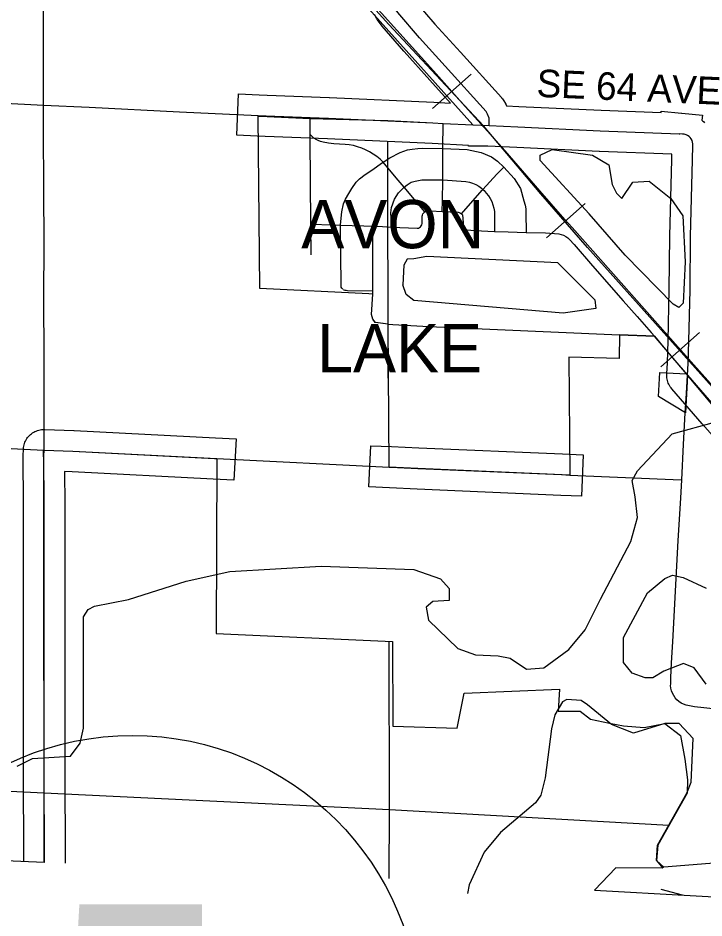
# Model space of a CAD drawing. Extents: x -1403959 to 81668, y -1400582 to 11018.
# Drawn here: x 7735.1 to 7831.3, y 7708.3 to 7834.6 of the extents above; entities that cross this region are included whole.
import ezdxf

# ---------------------------------------------------------------- set-up
doc = ezdxf.new("R2010")
doc.units = 0
for name, color, linetype in [('tdCiCityCartoExten', 7, 'Continuous'), ('tdCiCityDivCarto', 7, 'Continuous'), ('tdCiCoBndryTxt', 7, 'Continuous'), ('tdCiMapFrame', 7, 'Continuous'), ('tdCiRRCL', 7, 'Continuous'), ('tdCiSectLine', 7, 'Continuous'), ('tdCiSectNmbr', 7, 'Continuous'), ('tdCiSectTwpRng', 7, 'Continuous'), ('tdCoCityStreetMajor', 7, 'Continuous'), ('tdCoCityStreetMinor', 7, 'Continuous'), ('tdCoClipBndry', 7, 'Continuous'), ('tdCoSecRteBand', 7, 'Continuous'), ('tdCoSectNmbr', 7, 'Continuous'), ('tdCoStrucSecCoName', 7, 'Continuous'), ('tdCoSurfAsphalt', 7, 'Continuous'), ('tdCoSurfBitum', 7, 'Continuous')]:
    doc.layers.add(name, color=color, linetype=linetype)

msp = doc.modelspace()

# ---------------------------------------------------------------- linework, layer by layer
at = {"layer": 'tdCiCityCartoExten'}
for points in [[(7780.66, 7796.51), (7780.75, 7796.45), (7780.91, 7796.39), (7781.08, 7796.38), (7781.28, 7796.35)], [(7762.61, 7772.78), (7762.8, 7772.77), (7762.93, 7772.77)], [(7787.19, 7771.56), (7787.3, 7771.56)], [(7811.3, 7770.52), (7811.35, 7770.52)], [(7811.35, 7770.52), (7812.44, 7770.47)]]:
    msp.add_lwpolyline(points, dxfattribs=at)
at = {"layer": 'tdCiCityDivCarto'}
for points in [[(7776.02, 7820.49), (7776.06, 7820.6)], [(7776.17, 7801.37), (7776.14, 7805.6), (7776.14, 7805.66), (7776.06, 7817.66), (7776.05, 7818.21), (7776.02, 7820.49)], [(7794.63, 7811.87), (7794.64, 7816.28), (7794.69, 7819.77)], [(7786.25, 7814.38), (7785.84, 7814.77), (7785.37, 7815.15), (7784.87, 7815.49), (7784.36, 7815.8), (7783.82, 7816.07), (7783.27, 7816.31), (7782.7, 7816.5), (7782.12, 7816.66), (7781.53, 7816.77), (7780.93, 7816.84), (7780.15, 7816.86), (7779.38, 7816.91), (7778.61, 7817), (7777.84, 7817.13), (7777.5, 7817.23), (7777.17, 7817.36), (7776.86, 7817.53), (7776.57, 7817.73), (7776.3, 7817.95), (7776.05, 7818.21)], [(7787.19, 7814.94), (7788.66, 7815.71), (7789.67, 7816.08), (7790.33, 7816.19), (7791.14, 7816.27), (7791.78, 7816.33), (7794.64, 7816.28)], [(7794.64, 7816.28), (7798.06, 7816.1), (7800, 7815.69), (7801.45, 7815.07), (7802.33, 7814.49), (7803.18, 7813.66), (7804.64, 7812.07), (7805.53, 7810.65), (7806.01, 7808.92), (7806.17, 7808.33), (7806.26, 7807.82), (7806.29, 7807.26), (7806.34, 7804.5)], [(7780.6, 7796.55), (7780.49, 7796.67), (7780.41, 7796.82), (7780.37, 7796.99), (7780.37, 7797.16), (7780.29, 7805.52), (7780.29, 7805.54), (7780.46, 7807.37), (7780.71, 7808.51), (7781.01, 7809.15), (7781.46, 7809.96), (7781.87, 7810.63), (7782.51, 7811.52), (7782.94, 7811.99), (7783.73, 7812.6), (7784.71, 7813.22), (7786.16, 7814.29)], [(7786.16, 7814.29), (7786.28, 7814.36), (7787.19, 7814.94)], [(7788.12, 7812.14), (7786.28, 7814.36), (7786.25, 7814.38)], [(7797.25, 7807.1), (7800.17, 7810.43), (7800.25, 7810.51), (7802.23, 7812.65), (7803.18, 7813.66)], [(7789.21, 7810.83), (7788.12, 7812.14)], [(7789.18, 7810.81), (7789.21, 7810.83), (7789.64, 7811.18), (7790.22, 7811.53), (7790.75, 7811.7), (7791.72, 7811.86), (7792.59, 7811.85), (7793.64, 7811.87), (7794.63, 7811.87)], [(7794.57, 7807.42), (7794.57, 7807.45), (7794.61, 7808.87), (7794.63, 7811.87)], [(7794.63, 7811.87), (7794.63, 7811.87), (7797.89, 7811.65), (7798.36, 7811.54), (7798.81, 7811.39), (7799.25, 7811.2), (7799.67, 7810.96), (7800.06, 7810.69), (7800.25, 7810.51), (7800.42, 7810.37), (7800.74, 7810.02), (7801.04, 7809.64), (7801.29, 7809.24), (7801.5, 7808.81), (7801.67, 7808.36), (7801.79, 7807.9), (7801.87, 7807.43), (7801.9, 7806.95), (7801.9, 7805.42), (7801.9, 7804.67)], [(7787.41, 7805.24), (7787.41, 7805.26), (7787.38, 7806.54), (7787.37, 7807.22), (7787.44, 7807.98), (7787.88, 7809.15), (7788.41, 7810.04), (7788.69, 7810.32), (7789.18, 7810.81)], [(7792.1, 7807.36), (7789.21, 7810.83)], [(7787.41, 7805.24), (7787.41, 7805.24), (7789.84, 7805.12), (7791.06, 7805.07), (7791.23, 7805.1), (7791.38, 7805.17), (7791.51, 7805.28), (7791.62, 7805.41), (7791.69, 7805.56), (7791.73, 7805.72), (7791.76, 7805.89), (7791.75, 7806.75), (7791.78, 7806.93), (7791.86, 7807.1), (7791.96, 7807.24), (7792.1, 7807.36)], [(7792.1, 7807.36), (7792.27, 7807.46), (7792.46, 7807.52), (7792.89, 7807.5), (7794.57, 7807.42)], [(7792.1, 7807.36), (7792.1, 7807.36)], [(7794.57, 7807.42), (7796.77, 7807.31), (7796.95, 7807.28), (7797.11, 7807.21), (7797.25, 7807.1), (7797.32, 7807.03), (7797.38, 7806.94), (7797.54, 7805.31), (7797.57, 7805.17), (7797.64, 7805.05), (7797.74, 7804.95), (7797.86, 7804.89), (7798, 7804.86), (7799.14, 7804.77), (7801.9, 7804.64), (7803.8, 7804.56), (7806.34, 7804.49)], [(7776.14, 7805.66), (7779.15, 7805.54), (7780.29, 7805.52), (7783.57, 7805.43), (7784.88, 7805.37), (7786.2, 7805.31), (7787.41, 7805.24)], [(7784.84, 7796.28), (7784.85, 7804.15), (7784.88, 7805.37)], [(7801.9, 7804.67), (7801.9, 7804.64)], [(7806.34, 7804.49), (7806.34, 7804.49)], [(7806.34, 7804.49), (7809.05, 7804.42), (7810.89, 7804.3), (7811.23, 7804.22), (7811.56, 7804.1), (7811.87, 7803.93), (7812.15, 7803.73), (7812.41, 7803.49), (7813.06, 7802.81), (7815.63, 7799.8), (7819.93, 7794.92), (7821.9, 7792.71), (7823.84, 7790.48), (7824.32, 7789.92)], [(7781.28, 7796.35), (7784.84, 7796.28)], [(7786.98, 7791.64), (7785.15, 7791.86), (7784.81, 7792.34), (7784.63, 7792.99), (7784.81, 7795.84)], [(7784.81, 7795.84), (7784.84, 7796.28)], [(7784.84, 7796.28), (7784.84, 7796.28)], [(7786.98, 7791.64), (7787.62, 7791.56)], [(7787.62, 7791.56), (7792.66, 7791.3), (7819.41, 7790.13)], [(7819.41, 7790.13), (7824.32, 7789.92)], [(7824.32, 7789.92), (7824.32, 7789.92)], [(7824.32, 7789.92), (7824.32, 7789.92)], [(7824.32, 7789.92), (7824.97, 7789.17), (7826.83, 7786.92), (7828.94, 7784.47)], [(7828.64, 7779.19), (7828.79, 7781.91), (7828.94, 7784.47)]]:
    msp.add_lwpolyline(points, dxfattribs=at)
at = {"layer": 'tdCiCoBndryTxt'}
for points in [[(7801.15, 7819.51), (7801.15, 7820.5), (7800.92, 7821.09), (7800.7, 7821.46), (7794.97, 7827.8), (7791.36, 7831.8), (7788.34, 7835.32), (7787.85, 7835.99), (7787.55, 7836.51), (7787.34, 7837.19), (7787.12, 7838.96), (7787.12, 7847.33), (7787.04, 7868.63)], [(7768.77, 7820.9), (7769.87, 7820.85), (7776.06, 7820.6), (7778.6, 7820.5), (7786.93, 7820.13), (7786.97, 7820.13), (7793.26, 7819.85), (7794.69, 7819.78), (7798.86, 7819.58)], [(7768.77, 7820.9), (7768.77, 7820.9)], [(7798.86, 7819.58), (7801.15, 7819.47), (7805.17, 7819.28), (7816.7, 7818.74), (7827.77, 7818.34), (7827.86, 7818.33)], [(7801.15, 7819.48), (7801.15, 7819.51)], [(7828.94, 7784.47), (7829.04, 7786.09), (7829.14, 7789.24), (7829.3, 7796.44), (7829.39, 7803.9), (7829.53, 7809.29), (7829.65, 7814.68), (7829.69, 7816.67), (7829.7, 7816.91), (7829.66, 7817.15), (7829.59, 7817.38), (7829.48, 7817.6), (7829.33, 7817.79), (7829.16, 7817.96), (7828.96, 7818.1), (7828.74, 7818.2), (7828.5, 7818.26), (7828.26, 7818.29), (7827.86, 7818.33)], [(7828.94, 7784.47), (7833.19, 7779.56), (7835.35, 7777.09)], [(7738.75, 7725.79), (7738.75, 7729.7), (7738.73, 7736.55), (7738.75, 7744.39), (7738.75, 7751.36), (7738.73, 7758.63), (7738.73, 7766.39), (7738.7, 7773.1), (7738.73, 7773.96)]]:
    msp.add_lwpolyline(points, dxfattribs=at)
at = {"layer": 'tdCiMapFrame'}
for points in [[(7738.73, 7773.96), (7738.76, 7773.96), (7742.78, 7773.81), (7762.61, 7772.78)], [(7787.3, 7771.56), (7791.16, 7771.39), (7811.3, 7770.52)], [(7738.78, 7716.15), (7738.79, 7716.69), (7738.78, 7721.34), (7738.75, 7724.47), (7738.75, 7725.79)]]:
    msp.add_lwpolyline(points, dxfattribs=at)
at = {"layer": 'tdCiRRCL'}
msp.add_line((7717.09, 7717.17), (7738.73, 7716.16), dxfattribs=at)
for points in [[(7832.36, 7780.41), (7828.95, 7784.48), (7828.66, 7779.19), (7824.89, 7781.46), (7825.08, 7784.84), (7828.8, 7784.65), (7824.32, 7789.92), (7819.41, 7790.13), (7819.37, 7786.8), (7812.33, 7787.02), (7812.44, 7770.47), (7791.16, 7771.39), (7787.12, 7771.57), (7786.98, 7791.64), (7785.19, 7791.86), (7784.81, 7792.34), (7784.63, 7792.99), (7784.81, 7795.84), (7784.26, 7795.88), (7768.98, 7796.63), (7768.77, 7820.8), (7768.99, 7820.79), (7776.02, 7820.49), (7786.93, 7820.19), (7793.26, 7819.85), (7794.69, 7819.78), (7798.86, 7819.58), (7787.09, 7832.71), (7753.59, 7870.1)], [(7738.73, 7716.16), (7738.75, 7724.1), (7738.71, 7759.16), (7738.71, 7771.98), (7738.63, 7773.96), (7738.76, 7773.96), (7742.78, 7773.81), (7762.94, 7772.77), (7762.85, 7748.24), (7787.59, 7747.1), (7787.62, 7735.26), (7796.65, 7734.95), (7797.62, 7739.89), (7810.99, 7740.43), (7810.81, 7737.35), (7813.89, 7737.35), (7815.34, 7736.23), (7818.01, 7735.69), (7819.96, 7735.29), (7822.86, 7735.04), (7825.76, 7735.63), (7827.96, 7733.93), (7828.57, 7730.63), (7828.94, 7727.73), (7828.88, 7725.87), (7824.77, 7718.54), (7824.62, 7716.4), (7825.48, 7715.32), (7818.9, 7715.4), (7815.93, 7712.27)], [(7815.93, 7712.27), (7882.99, 7708.51), (7883.79, 7708.47)]]:
    msp.add_lwpolyline(points, dxfattribs=at)
at = {"layer": 'tdCiSectLine'}
for points in [[(7790.62, 7837.12), (7793.54, 7833.71), (7797.12, 7829.75), (7797.12, 7829.75), (7802.85, 7823.4), (7802.88, 7823.37), (7803, 7823.22), (7803.11, 7823.07), (7803.2, 7822.93), (7803.42, 7822.56), (7803.43, 7822.54), (7803.52, 7822.37), (7803.57, 7822.26), (7805.31, 7822.17), (7816.82, 7821.63), (7825.24, 7821.33), (7825.25, 7821.5), (7828.09, 7821.22), (7828.14, 7821.22), (7831.03, 7820.94), (7830.96, 7820.23), (7831.07, 7820.14), (7831.17, 7820.05), (7831.34, 7819.88)], [(7833.18, 7775.17), (7831.01, 7777.65), (7830.99, 7777.66), (7826.75, 7782.58), (7826.64, 7782.71), (7826.53, 7782.86), (7826.43, 7783.02), (7826.34, 7783.19), (7826.26, 7783.36), (7826.2, 7783.54), (7826.14, 7783.72), (7826.1, 7783.91), (7826.07, 7784.1), (7826.05, 7784.28), (7826.04, 7784.47), (7826.05, 7784.65), (7826.14, 7786.22), (7826.24, 7789.31), (7826.39, 7796.49), (7826.49, 7803.94), (7826.49, 7803.98), (7826.63, 7809.36), (7826.74, 7814.74), (7826.74, 7814.75), (7826.76, 7815.47), (7816.6, 7815.84), (7816.57, 7815.84), (7805.04, 7816.38), (7805.03, 7816.38), (7800.95, 7816.57), (7798.24, 7816.58), (7798.24, 7816.7), (7793.13, 7816.95), (7778.48, 7817.6), (7769.75, 7817.95), (7769.74, 7817.95), (7768.63, 7818), (7765.74, 7818.13), (7766, 7823.93), (7768.9, 7823.8), (7769.99, 7823.75), (7778.72, 7823.4), (7778.73, 7823.4), (7793.39, 7822.75), (7793.4, 7822.75), (7795.73, 7822.64), (7792.82, 7825.86), (7789.21, 7829.85), (7789.18, 7829.88), (7789.16, 7829.91), (7786.13, 7833.43), (7786.04, 7833.56), (7785.99, 7833.62), (7785.5, 7834.29), (7785.44, 7834.38), (7785.34, 7834.53), (7785.04, 7835.05)], [(7735.88, 7716.29), (7735.89, 7716.72), (7735.88, 7721.32), (7735.85, 7724.44), (7735.85, 7724.47), (7735.85, 7729.7), (7735.83, 7736.55), (7735.83, 7736.55), (7735.83, 7736.56), (7735.85, 7744.4), (7735.85, 7751.36), (7735.83, 7758.62), (7735.83, 7758.63), (7735.83, 7766.38), (7735.8, 7773.08), (7735.8, 7773.1), (7735.8, 7773.19), (7735.83, 7774.05), (7735.83, 7774.15), (7735.85, 7774.34), (7735.88, 7774.53), (7735.92, 7774.71), (7735.98, 7774.89), (7736.05, 7775.07), (7736.12, 7775.24), (7736.21, 7775.41), (7736.31, 7775.57), (7736.42, 7775.73), (7736.54, 7775.87), (7736.67, 7776.01), (7736.81, 7776.14), (7736.96, 7776.26), (7737.11, 7776.37), (7737.28, 7776.47), (7737.44, 7776.56), (7737.62, 7776.64), (7737.79, 7776.71), (7737.98, 7776.76), (7738.16, 7776.81), (7738.35, 7776.84), (7738.54, 7776.86), (7738.73, 7776.86), (7738.83, 7776.86), (7742.89, 7776.71), (7742.93, 7776.71), (7762.76, 7775.68), (7765.65, 7775.53), (7765.35, 7769.74), (7762.46, 7769.89), (7742.65, 7770.91), (7741.61, 7770.95), (7741.63, 7766.4), (7741.63, 7766.39), (7741.63, 7758.63), (7741.65, 7751.37), (7741.65, 7751.36), (7741.65, 7744.39), (7741.65, 7744.39), (7741.63, 7736.55), (7741.65, 7729.71), (7741.65, 7729.7), (7741.65, 7724.48), (7741.68, 7721.36), (7741.68, 7721.35), (7741.7, 7716.7), (7741.7, 7716.69), (7741.7, 7716.63), (7741.68, 7716.02)], [(7814.07, 7767.49), (7811.17, 7767.62), (7791.04, 7768.49), (7791.04, 7768.49), (7787.17, 7768.66), (7784.27, 7768.79), (7784.53, 7774.58), (7787.43, 7774.46), (7791.29, 7774.29), (7811.43, 7773.42), (7814.32, 7773.29), (7814.07, 7767.49)]]:
    msp.add_lwpolyline(points, dxfattribs=at)
at = {"layer": 'tdCiSectNmbr'}
for points in [[(7715.34, 7823.57), (7738.64, 7822.36), (7738.67, 7822.36)], [(7738.73, 7773.96), (7738.76, 7775.15), (7738.73, 7780.03), (7738.75, 7786.95), (7738.7, 7795.3), (7738.72, 7802.95), (7738.7, 7810.45), (7738.64, 7818.96), (7738.64, 7822.35)], [(7738.67, 7822.36), (7745.06, 7822.04), (7757.7, 7821.41), (7768.77, 7820.9)], [(7828.14, 7769.79), (7828.39, 7774.75), (7828.64, 7779.19)], [(7762.93, 7772.77), (7762.94, 7772.77)], [(7762.94, 7772.77), (7787.12, 7771.57)], [(7787.12, 7771.57), (7787.19, 7771.56)], [(7812.44, 7770.47), (7828.08, 7769.79), (7828.14, 7769.79)], [(7832.99, 7737.63), (7829.95, 7737.97), (7828.74, 7738.19), (7828.39, 7738.32), (7828.06, 7738.49), (7827.75, 7738.7), (7827.47, 7738.94), (7827.22, 7739.22), (7827.01, 7739.53), (7826.84, 7739.86), (7826.71, 7740.21), (7826.62, 7740.57), (7826.58, 7740.94), (7826.59, 7741.15), (7826.61, 7742.05), (7826.72, 7744.14), (7826.89, 7747.08), (7827.23, 7753.3), (7827.64, 7761.31), (7828.01, 7767.24), (7828.14, 7769.79)]]:
    msp.add_lwpolyline(points, dxfattribs=at)
at = {"layer": 'tdCiSectTwpRng'}
for points in [[(7738.64, 7822.35), (7738.64, 7822.36), (7738.63, 7836.8)], [(7693.9, 7776.27), (7714, 7775.24), (7738.63, 7773.96), (7738.73, 7773.96)], [(7825.23, 7712.37), (7828.21, 7711.58)]]:
    msp.add_lwpolyline(points, dxfattribs=at)
at = {"layer": 'tdCoCityStreetMajor'}
for points in [[(7787, 7784.05), (7786.91, 7817.29)], [(7787.16, 7723.57), (7787.1, 7747.13)], [(7741.62, 7725.76), (7787.16, 7723.57)], [(7787.12, 7713.89), (7787.16, 7723.57)], [(7787.16, 7723.57), (7826.33, 7721.37)]]:
    msp.add_lwpolyline(points, dxfattribs=at)
at = {"layer": 'tdCoCityStreetMinor'}
msp.add_lwpolyline([(7741.62, 7725.76), (7787.16, 7723.57), (7826.33, 7721.37)], dxfattribs=at)
at = {"layer": 'tdCoClipBndry'}
msp.add_lwpolyline([(7570.28, 7733.79), (7594.28, 7732.69), (7690.48, 7728.22), (7741.62, 7725.76), (7787.16, 7723.57), (7826.33, 7721.37)], dxfattribs=at)
at = {"layer": 'tdCoSecRteBand'}
for p, q in [((7798.61, 7826.68), (7793.19, 7821.86)), ((7814.62, 7808.56), (7809.2, 7803.74)), ((7830.65, 7790.44), (7825.21, 7785.64))]:
    msp.add_line(p, q, dxfattribs=at)
for points in [[(7800.33, 7819.43), (7787.05, 7833.65), (7766.84, 7856.02), (7752.23, 7872.31), (7741.73, 7883.63), (7733.79, 7891.61), (7729.07, 7896.59), (7723.52, 7901.66), (7721.81, 7902.83), (7717.54, 7905.21), (7713.1, 7907.32), (7710.44, 7908.41), (7707.15, 7909.46), (7701.25, 7910.95), (7699.27, 7911.26), (7694.85, 7911.96), (7689.1, 7912.84), (7684.99, 7913.49), (7678.19, 7914.91), (7673.7, 7916.36)], [(7835.3, 7779.79), (7829.44, 7786.33), (7822.9, 7793.74), (7818.21, 7799.06), (7812.78, 7805.17), (7811.77, 7806.31), (7808.22, 7810.32), (7803.4, 7815.95), (7800.46, 7819.22), (7797.79, 7822.14), (7793.33, 7827.16), (7791.66, 7829.02), (7784.3, 7837.22)], [(7835.3, 7779.79), (7829.44, 7786.33), (7822.9, 7793.74), (7818.21, 7799.06), (7812.78, 7805.17), (7811.77, 7806.31), (7808.22, 7810.32), (7803.4, 7815.95), (7800.46, 7819.22), (7797.79, 7822.14), (7793.33, 7827.16), (7791.66, 7829.02), (7784.3, 7837.22)], [(7814.94, 7802.39), (7808.4, 7809.91), (7800.33, 7819.43)], [(7879.85, 7707.84), (7879.04, 7714.32), (7878.04, 7718.37), (7877.2, 7721.15), (7876.57, 7723.35), (7875.9, 7725.29), (7874.97, 7727.75), (7872.42, 7733.01), (7870.97, 7735.91), (7869.35, 7739.09), (7867.55, 7741.84), (7865.46, 7744.88), (7861.76, 7749.34), (7855.92, 7756.1), (7847.17, 7765.92), (7842.73, 7770.98), (7833.19, 7781.96), (7829.21, 7786.41), (7814.94, 7802.39)]]:
    msp.add_lwpolyline(points, dxfattribs=at)
at = {"layer": 'tdCoSurfAsphalt'}
msp.add_circle((7751.13, 7693.62), 40.33, dxfattribs=at)
at = {"layer": 'tdCoSurfBitum'}
for points in [[(7827.71, 7793.97), (7826.95, 7794.43), (7820.22, 7801.29), (7815.17, 7807.09), (7808.29, 7814.57), (7808.29, 7815.33), (7809.97, 7816.1), (7815.62, 7815.34), (7817.92, 7813.97), (7818.38, 7811.22), (7818.99, 7810), (7819.75, 7809.23), (7821.28, 7811.53), (7823.57, 7811.68), (7826.63, 7809.24), (7828.31, 7806.8), (7828.62, 7800.38), (7828.32, 7794.58), (7827.71, 7793.97)], [(7790.57, 7800.81), (7789.65, 7800.73), (7789.18, 7799.9), (7789.02, 7797.15)], [(7815.95, 7795.03), (7810.75, 7800.22), (7792.4, 7801.11), (7790.57, 7800.81)], [(7790.57, 7794.94), (7789.48, 7795.78), (7789.02, 7797.15)], [(7815.95, 7795.03), (7816.1, 7793.81), (7811.52, 7793.19), (7790.57, 7794.94)], [(7734.95, 7729.66), (7737.09, 7730.73), (7742.44, 7731.03), (7743.81, 7732.86), (7744.27, 7734.99), (7744.28, 7750.56), (7744.9, 7751.63), (7745.81, 7752.09), (7750.55, 7753), (7758.65, 7755.58), (7764.76, 7756.95), (7777.6, 7757.69), (7790.58, 7757.22), (7794.3, 7755.92), (7795.53, 7754.55), (7795.53, 7752.87), (7793.24, 7752.72), (7792.32, 7751.95), (7792.63, 7750.12), (7796.76, 7746.15), (7799.2, 7745.24), (7802.41, 7745.09), (7804.09, 7744.78), (7806.38, 7743.26), (7808.82, 7743.41), (7812.33, 7746.01), (7814.62, 7748.76), (7816.76, 7753.04), (7821.02, 7761.14), (7821.94, 7764.5), (7821.63, 7767.4), (7821.17, 7769.69), (7821.93, 7771.06), (7826.81, 7776.26), (7832.92, 7777.94)], [(7831.58, 7741.14), (7829.9, 7743.43), (7828.37, 7744.04), (7825.63, 7742.97), (7824.1, 7742.05), (7823.03, 7742.05), (7821.2, 7742.66), (7819.97, 7744.19), (7819.97, 7747.7), (7823.32, 7753.96), (7825.77, 7755.95), (7826.83, 7756.41), (7828.36, 7756.1), (7831.57, 7754.58)], [(7835.58, 7716.26), (7825.65, 7715.48), (7824.58, 7716.4), (7824.73, 7718.54), (7828.85, 7725.87), (7829.46, 7727.4), (7829.76, 7733.51), (7827.77, 7735.64), (7825.79, 7735.64), (7821.36, 7734.26), (7818.3, 7735.48), (7814.94, 7738.23), (7814.02, 7738.84), (7812.04, 7738.99), (7811.43, 7738.68), (7810.36, 7736.85), (7809.9, 7734.86), (7808.99, 7727.99), (7808.38, 7725.55), (7807.62, 7724.48), (7802.74, 7720.35), (7800.45, 7717.6), (7798.32, 7713.02), (7798.12, 7711.78)]]:
    msp.add_lwpolyline(points, dxfattribs=at)

# ---------------------------------------------------------------- texts
at = {"layer": 'tdCoSectNmbr'}
msp.add_text('SE 64 AVE', height=3.869, rotation=357.5187, dxfattribs=at).set_placement((7807.73, 7823.51))
at = {"layer": 'tdCoStrucSecCoName'}
for s, p in [('AVON', (7774.79, 7802.27)), ('AVON', (7774.79, 7802.27)), ('  LAKE', (7771.98, 7784.86)), ('  LAKE', (7771.98, 7784.86))]:
    msp.add_text(s, height=6.771, rotation=0.0002, dxfattribs=at).set_placement(p)
at = {"layer": 'tdCoSurfAsphalt'}
msp.add_text('5', height=32.89, dxfattribs=at).set_placement((7740.03, 7677.39))

doc.saveas('drawing.dxf')
